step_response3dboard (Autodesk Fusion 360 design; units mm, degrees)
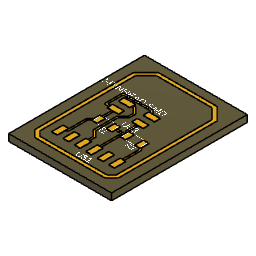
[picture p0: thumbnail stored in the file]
sketch "Outline" plane through (0, 0, 0) normal (0, 0, 1) x axis (1, 0, 0)
  line L1 (45.7, 66.04) -> (22.86, 66.04)
  line L2 (45.7, 96.19) -> (45.7, 66.04)
  line L3 (22.86, 96.19) -> (45.7, 96.19)
  line L4 (22.86, 66.04) -> (22.86, 96.19)
canvas "Canvas1"
canvas "Canvas2"
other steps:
pcbextrude "PCBExtrude1"
extrude "Extrude1" sketch "Outline" blind 1.5 bodies "Board"
pcbextrude "PCBExtrude1"
pcbextrude "PCBExtrude1"
pcbextrude "PCBExtrude"
create_component "CreateComponent1"
create_component "CreateComponent2"
create_component "CreateComponent3"
create_component "CreateComponent4"
as_built_joint "As-built1"
named bodies: "Board"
